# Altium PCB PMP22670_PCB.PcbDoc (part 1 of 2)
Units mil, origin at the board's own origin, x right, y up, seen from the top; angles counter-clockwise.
Board outline 3010.03 x 2810.03 mil, 4 copper layers (Top Layer, GND Layer, Signal Layer, Bottom Layer), stack 61.2 mil thick; 62 components, 17 nets, 102 pads, 238 vias.
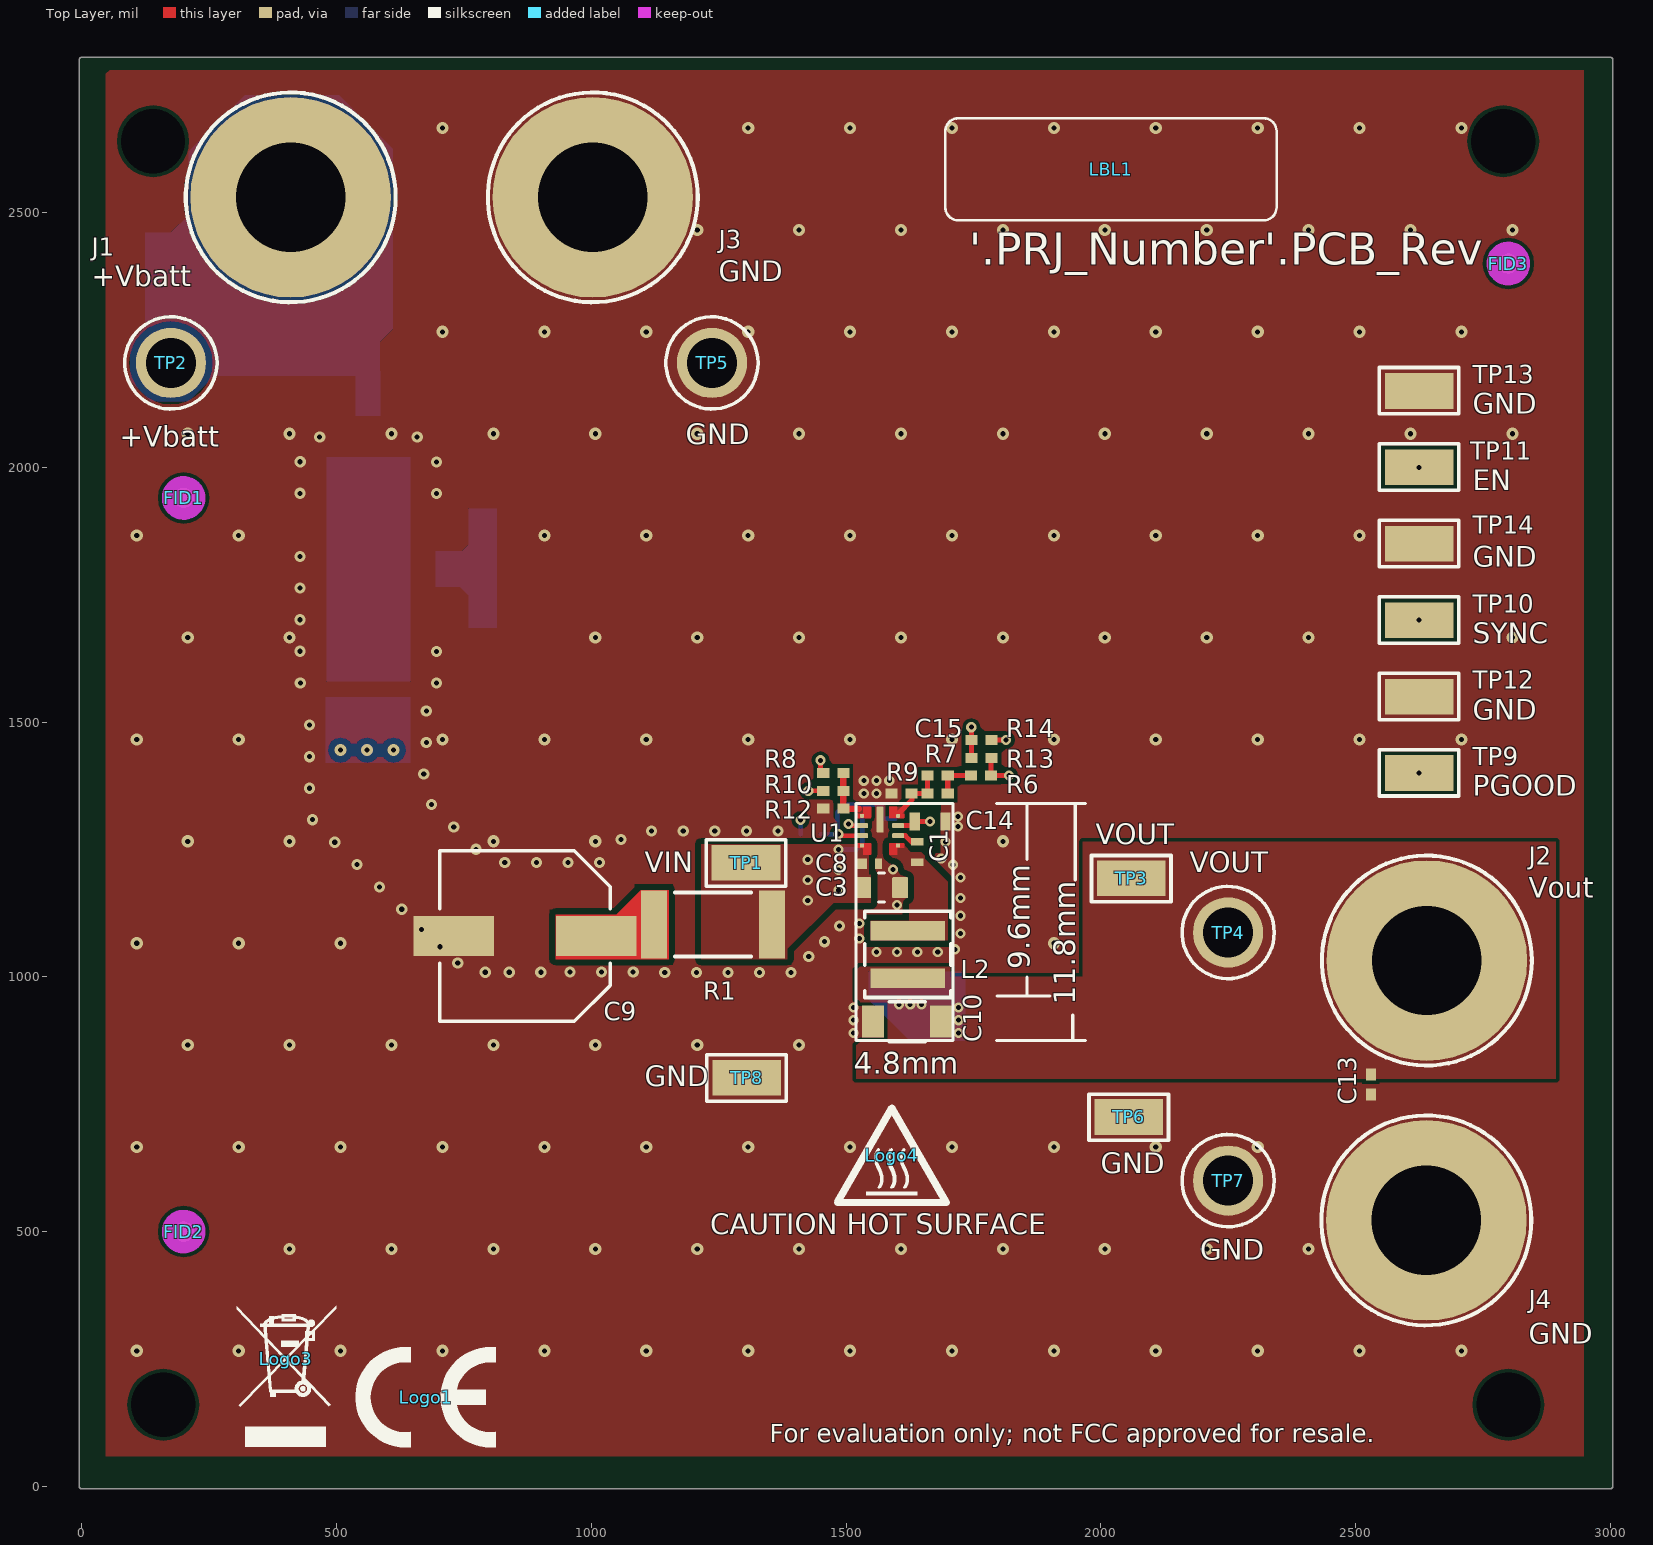
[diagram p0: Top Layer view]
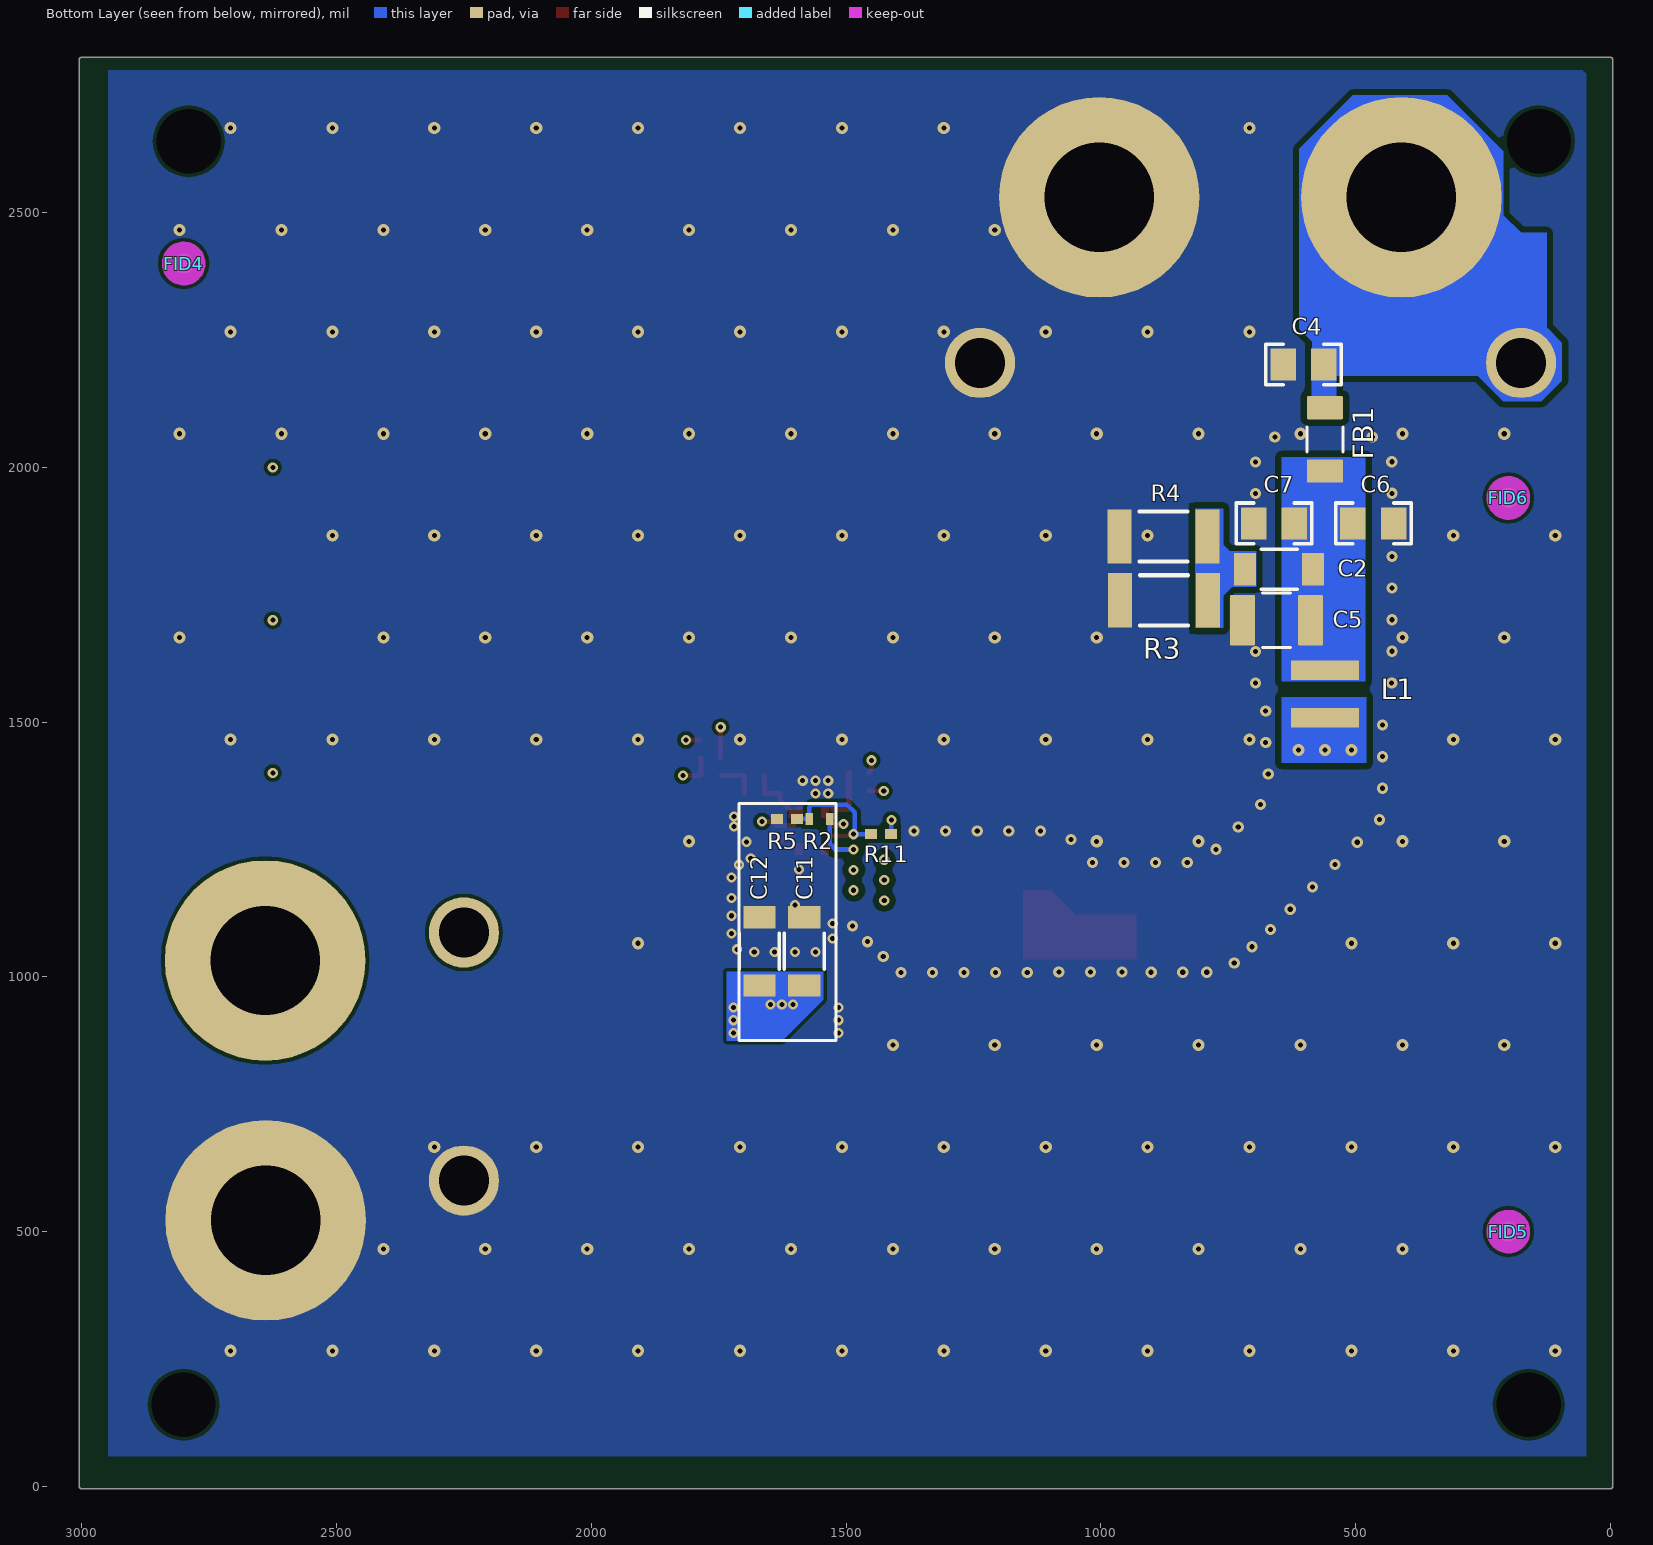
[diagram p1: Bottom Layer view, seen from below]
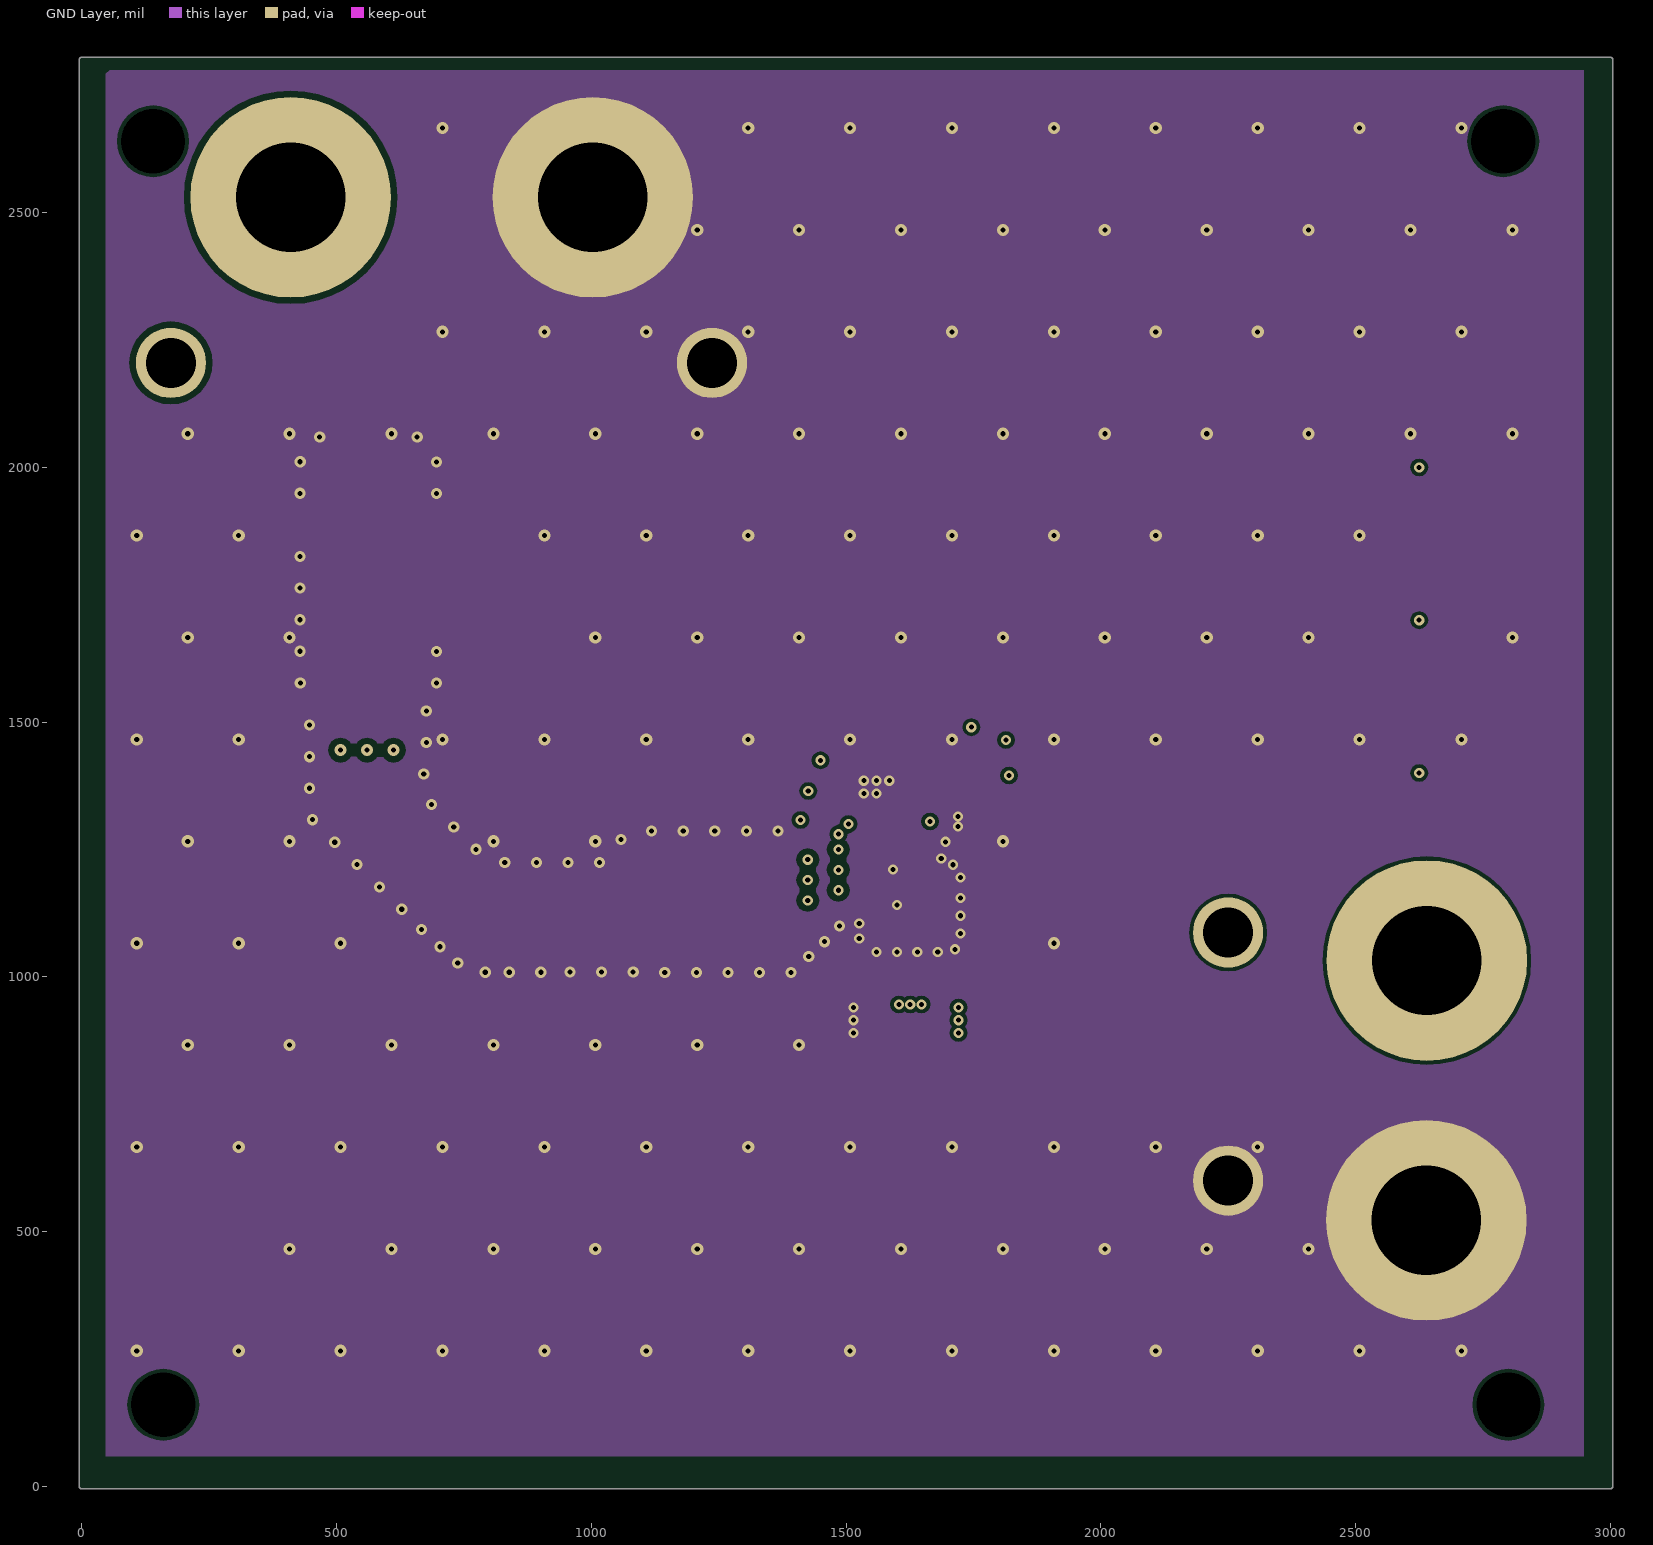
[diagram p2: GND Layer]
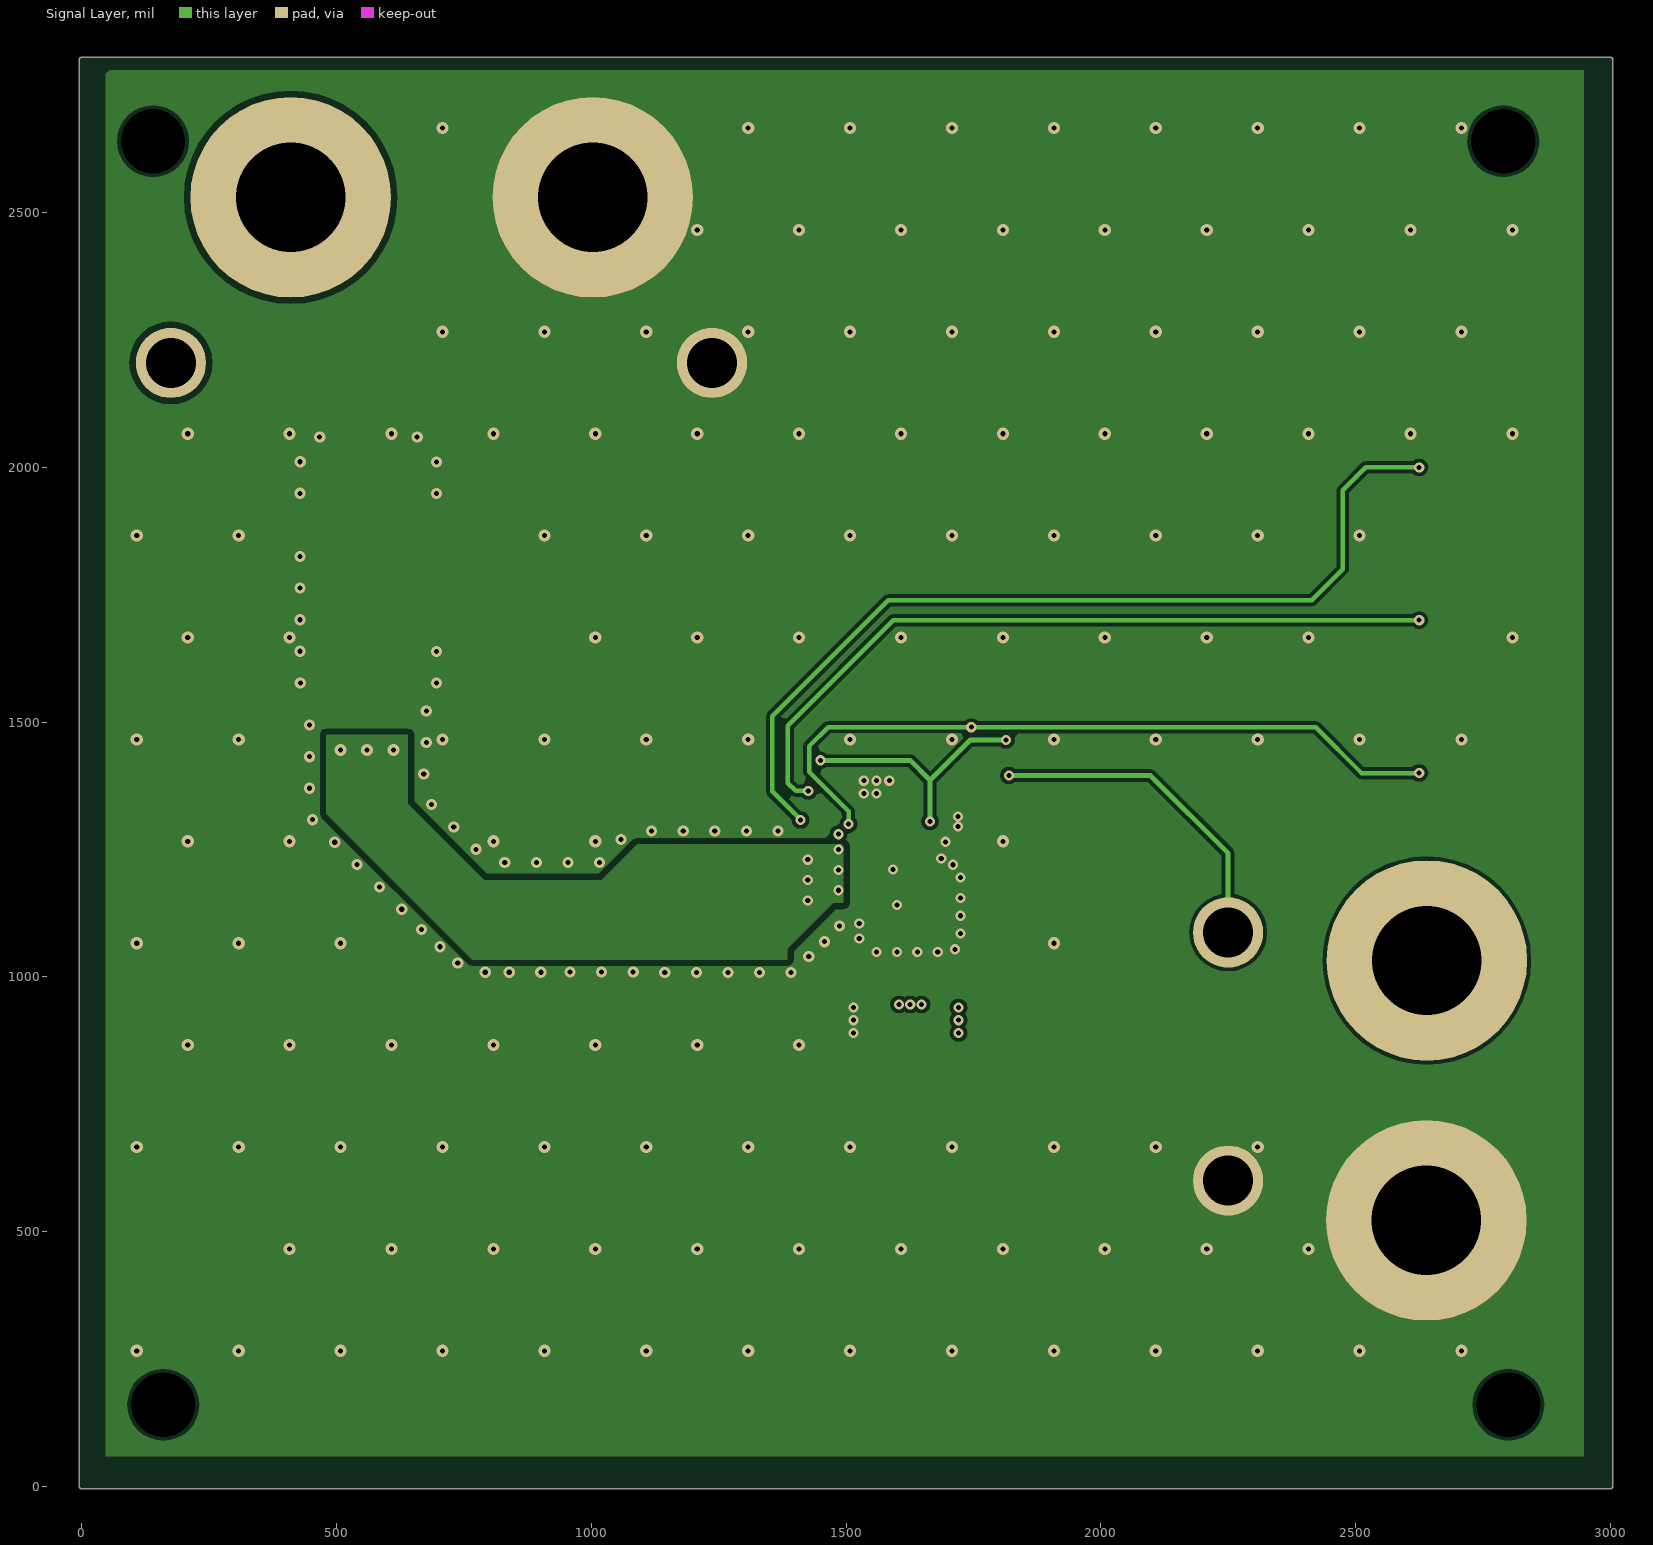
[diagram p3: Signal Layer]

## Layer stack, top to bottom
Top Solder: solder mask 0.4, Solder Resist, Dk 3.5
Top Layer: signal copper 1.4
Dielectric1: core 12.5, FR-4 High Tg, Dk 4.2
GND Layer: signal copper 0.7
Dielectric 2: prepreg 32, FR-4 High Tg, Dk 4.2
Signal Layer: signal copper 0.7
Dielectric 3: core 12.5, FR-4 High Tg, Dk 4.2
Bottom Layer: signal copper 1.4
Bottom Solder: solder mask 0.4, Solder Resist, Dk 3.5

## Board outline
0,-5.02 cw(c0,0) -5.01,0 -5.01,2800 cw(c0,2800) 0,2805.02 2999,2805.02 cw(c2999,2800) 2999.5,2804.99 cw(c3000,2800) 3005.01,2800 3005.01,0 cw(c3000,0) 3000,-5.02

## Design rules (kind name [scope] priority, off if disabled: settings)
AcuteAngle [All] p1: minimum=4.50000000000000E+0001 checktracksonly=FALSE
AssemblyTestPointUsage [All] p1: valid=2
BoardOutlineClearance BoardOutlineClearance_MountingHoles [OnCopper and InComponentClass('Mounting Holes')] p1: gap=40 ignorepadtopadclearanceinfootprint=FALSE
BoardOutlineClearance BoardOutlineClearance_Poly [OnCopper and IsPoly] p2: gap=25 ignorepadtopadclearanceinfootprint=FALSE
BoardOutlineClearance [OnCopper and Not InComponentClass('Logo') and not InComponentClass('FiducialMark') and not InRegion(1000,500,4000,800) and not InPoly] p3: gap=30 ignorepadtopadclearanceinfootprint=FALSE
Clearance Clearance_BottomLayer_Vin [InNamedPolygon('BOTTOM_LAYER_GND') vs (InNet('Vin') OR InNet('VINY') OR InNet('NetC2_2') OR InNet('VINX'))] p1: gap=12 ignorepadtopadclearanceinfootprint=FALSE
Clearance Clearance_SW_1 [InNamedPolygon('TOP_LAYER_SW') vs InNet('GND')] p2: gap=12 ignorepadtopadclearanceinfootprint=FALSE
Clearance Clearance_TopLayer_GND [InNamedPolygon('TOP_LAYER_GND') vs (InNet('Vin') OR InNet('VINX') OR InNet('SW'))] p3: gap=12 ignorepadtopadclearanceinfootprint=FALSE
Clearance Clearance_Midlayer2_GND [InNamedPolygon('SIGNAL_LAYER_GND') vs (InNet('Vin') OR InNet('VINX'))] p4: gap=12 ignorepadtopadclearanceinfootprint=FALSE
Clearance Clearance_Midlayer1_Vin [InNamedPolygon('GND_LAYER_GND') vs (InNet('Vin') OR InNet('VINX'))] p5: gap=12 ignorepadtopadclearanceinfootprint=FALSE
Clearance Clearance_NetC91 [InNamedPolygon('TOP_LAYER_GND') vs InNet('NetC9_1')] p6: gap=12 ignorepadtopadclearanceinfootprint=FALSE
Clearance Clearance_Vin [(InNamedPolygon('Top Layer-Vin')) vs InNet('GND')] p7: gap=12 ignorepadtopadclearanceinfootprint=FALSE
Clearance Clearance_VinPolygon [(InNet('Vin') AND InNamedPolygon('Top Layer-Vin')) vs (InNet('GND') OR InNet('PGOOD'))] p8: gap=12 ignorepadtopadclearanceinfootprint=FALSE
Clearance Clearance_Keepouts [((IsTrack Or IsArc) And Not InPoly) And IsFree and IsKeepOut vs ((IsTrack Or IsArc) And Not InPoly) And IsFree and IsKeepOut] p9: gap=0 ignorepadtopadclearanceinfootprint=FALSE
Clearance Clearance_Poly [InPolygon] p10: gap=7 ignorepadtopadclearanceinfootprint=FALSE
Clearance Clearance_FiducialMark [IsKeepOut and InComponentClass('FiducialMark') vs IsPad and InComponentClass('FiducialMark')] p11: gap=0 ignorepadtopadclearanceinfootprint=FALSE
Clearance [All] p12: gap=7.5 ignorepadtopadclearanceinfootprint=FALSE except(0: Arc-Hole Track-Hole SMDPad-Hole THPad-Hole Via-Hole Fill-Hole Poly-Hole Region-Hole Text-Hole)
ComponentClearance ComponentClearance_MountingHoles_FiducialMarks [InComponentClass('Mounting Holes') vs InComponentClass('FiducialMark')] p1: gap=50 collisioncheckmode=3 verticalgap=10 showdistances=FALSE
ComponentClearance ComponentClearance_Shunt [InComponentClass('Header') vs InComponentClass('Shunt')] p2: gap=0 collisioncheckmode=3 verticalgap=0 showdistances=FALSE
ComponentClearance ComponentClearance_Logo [InComponentClass('Logo')] p3: gap=50 collisioncheckmode=3 verticalgap=10 showdistances=FALSE
ComponentClearance ComponentClearance_ScrewToNut [(HasFootprint('NY PMS 440 0025 PH')) vs (HasFootprint('Keystone_1902C'))] p4: gap=5 collisioncheckmode=3 verticalgap=10 showdistances=FALSE
ComponentClearance ComponentClearance_MountingHoles [InComponentClass('Mounting Holes')] p5: gap=250 collisioncheckmode=3 verticalgap=100000 showdistances=FALSE
ComponentClearance ComponentClearance_SmallPassives [HasFootprint('0201*') or HasFootprint('0402*') or HasFootprint('0508') or HasFootprint('0603*') or HasFootprint('0612') or HasFootprint('0805*') or HasFootprint('0815*') or HasFootprint('0830*') or HasFootprint('1206*') or HasFootprint('1210*') or HasFootprint('1808*') or HasFootprint('1812*') or HasFootprint('1825*') or HasFootprint('2010*') or HasFootprint('2220*') or HasFootprint('2225*') or HasFootprint('2512*') or HasFootprint('2728*') or HasFootprint('3518*') vs HasFootprint('0201*') or HasFootprint('0402*') or HasFootprint('0508') or HasFootprint('0603*') or HasFootprint('0612') or HasFootprint('0805*') or HasFootprint('0815*') or HasFootprint('0830*') or HasFootprint('1206*') or HasFootprint('1210*') or HasFootprint('1808*') or HasFootprint('1812*') or HasFootprint('1825*') or HasFootprint('2010*') or HasFootprint('2220*') or HasFootprint('2225*') or HasFootprint('2512*') or HasFootprint('2728*') or HasFootprint('3518*')] p6: gap=10 collisioncheckmode=3 verticalgap=10 showdistances=FALSE
ComponentClearance ComponentClearance_THtoSMT [IsThruComponent vs IsSMTComponent] p7: gap=40 collisioncheckmode=3 verticalgap=30 showdistances=FALSE
ComponentClearance ComponentClearance_THtoTH [IsThruComponent vs IsThruComponent] p8: gap=30 collisioncheckmode=3 verticalgap=30 showdistances=FALSE
ComponentClearance [All] p9: gap=10 collisioncheckmode=3 verticalgap=10 showdistances=FALSE
DiffPairsRouting [All] p1: maxlimit=100 minlimit=10 mostfreqgap=10 toplayer_minwidth=15 toplayer_maxwidth=15 toplayer_prefwidth=15 midlayer1_minwidth=15 midlayer1_maxwidth=15 midlayer1_prefwidth=15 midlayer2_minwidth=15 midlayer2_maxwidth=15 midlayer2_prefwidth=15 bottomlayer_minwidth=15 bottomlayer_maxwidth=15 bottomlayer_prefwidth=15 maxuncoupledlength=1000
FabricationTestPointUsage TestPointUsage [All] p1: valid=2 allowmultiple=FALSE
FabricationTestpoint Testpoint [All] p1: side=3 testpointundercomponent=TRUE minsize=40 maxsize=100 preferedsize=60 minholesize=0 maxholesize=40 preferedholesize=32 testpointgrid=1 allowsidetop=TRUE allowsidebottom=TRUE usegrid=TRUE gridtolerance=0.01
FanoutControl Fanout_LCC [IsLCC] p1: bgadir=Out bgaviamode=Centered fanoutstyle=Auto fanoutdirection=Alternating viagrid=1 // Fanout_LCC (Default Rule)
FanoutControl Fanout_BGA [IsBGA] p2: bgadir=Out bgaviamode=Centered fanoutstyle=Auto fanoutdirection=Alternating viagrid=1 // Fanout_BGA (Default Rule)
FanoutControl Fanout_Default [All] p4: bgadir=Out bgaviamode=Centered fanoutstyle=Auto fanoutdirection=Alternating viagrid=1 // Fanout_Default (Default Rule)
FanoutControl Fanout_Small [(CompPinCount < 5)] p5: bgadir=Out bgaviamode=Centered fanoutstyle=Auto fanoutdirection=OutThenIn viagrid=1 // Fanout_Small (Default Rule)
HoleSize [All] p1: absolutevalues=TRUE maxlimit=251 minlimit=7.87 maxpercent=80.000 minpercent=20.000
MinimumAnnularRing MinimumAnnularRing_ThermalPadVias [IsVia and InAnyComponent] p1: minimumring=5
MinimumAnnularRing [All] p2: minimumring=5
MinimumSolderMaskSliver MinimumSolderMaskSliver_Logo [InComponentClass('Logo') vs InComponentClass('Logo')] p1: minsoldermaskwidth=0.7
MinimumSolderMaskSliver [All] p2: minsoldermaskwidth=3.94
PlaneClearance [All] p1: clearance=8
PlaneConnect [All] p1: planeconnectstyle=Direct reliefexpansion=10 reliefentries=4 reliefconductorwidth=10 reliefairgap=10
PolygonConnect [All] p1: connectstyle=Direct reliefconductorwidth=10 reliefentries=4 polygonreliefangle="90 Angle" airgapwidth=10
RoutingVias ThermalPadVias [IsVia and InAnyComponent] p1: holewidth=8 width=16 viastyle="Through Hole" minholewidth=7.87 minwidth=10 maxholewidth=12.99 maxwidth=30
RoutingVias [All] p2: holewidth=8 width=16 viastyle="Through Hole" minholewidth=7.87 minwidth=15 maxholewidth=40 maxwidth=65
SilkToBoardRegionClearance [Not ((IsComment or IsDesignator) And (Hide <> 'False')) and not InRegion(1000,500,4000,800)] p1:
SilkToSilkClearance SilkToSilkClearance_Pb-FreeLogo [(HasFootprint('Pb-Free_Overlay_Medium') OR HasFootprint('Pb-Free_Overlay_Small')) vs (HasFootprint('Pb-Free_Overlay_Medium') OR HasFootprint('Pb-Free_Overlay_Small'))] p1: silktosilkclearance=0
SilkToSilkClearance [All] p2: silktosilkclearance=0
SilkToSolderMaskClearance SilkToComponentPadClearance [(IsPad or IsFill or IsRegion) and InAnycomponent] p1: minsilkscreentomaskgap=0 clearancetoexposedcopper=TRUE
SilkToSolderMaskClearance "Silk to Solder Mask Opening" [All] p2: minsilkscreentomaskgap=0 clearancetoexposedcopper=FALSE
SolderMaskExpansion [All] p1: expansion=1.97
Width [All] p1: maxlimit=100 minlimit=6 preferedwidth=10
14 further rules are at their usual default settings.

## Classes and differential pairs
component class FiducialMark: FID1 FID2 FID3 FID4 FID5 FID6
component class PMP22670_Schematic: C1 C2 C3 C4 C5 C6 C7 C8 C9 C10 C11 C12 C13 C14 C15 CVCC FB1 J1 J2 J3 J4 L L1 L2 R1 R2 R3 R4 R5 R6 R7 R8 R9 R10 R11 R12 R13 R14 R? TP1 TP2 TP3 TP4 TP5 TP6 TP7 TP8 TP9 TP10 TP11 TP12 TP13 TP14 U1
component class Label: LBL1
component class PMP22670_Hardware: FID1 FID2 FID3 FID4 FID5 FID6 LBL1 Logo1 Logo2 Logo3 Logo4

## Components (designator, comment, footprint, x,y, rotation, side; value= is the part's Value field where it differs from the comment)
C1 "CGA2B3X7R1E104K050BB" 0402S 1640,1245 r270 top value=0.1uF
C2 "CGA5L2X7R2A105K160AA" 1206_180 650,1800 r0 bottom value=1uF
C3 "CGA4J1X7R1H475K125AC" FP-CGA4J1X7R1H475K125AC_0805-MFG 1570,1175 r180 top value=4.7µF
C4 "DNP" 0805_HV 602,2202 r0 bottom value=0.1uF
C5 "HMF325B7225KMHP" FP-HMF325B7225KMHP_1210-MFG 655,1700 r180 bottom
C6 "" 0805_HV 465,1890 r180 bottom value=0.1uF
C7 "" 0805_HV 660,1890 r0 bottom value=0.1uF
C8 "CGA2B3X7R1H104K050BB" 0402L#1 1549,1222 r0 top value=0.1uF
C9 "" SM_RADIAL_F 870,1080 r180 top value=22uF
C10 "" 1206_180 1620,912 r0 top value=22uF
C11 "" 1206_180 1582,1050 r270 bottom value=22uF
C12 "" 1206_180 1670,1050 r270 bottom value=22uF
C13 "GCM155R71H102KA37D" 0402L#2 2530,789 r90 top value=1000pF
C14 "CGA3E1X7R1C105K080AC" 0603S 1665,1305 r0 top value=1uF
C15 "DNP" 0402L#2 1680,1395 r180 top value=10pF
FB1 "BLM31KN471SH1L" FP-BLM31KN471SH1L_1206-MFG 560,2055 r270 bottom
FID1 "Fiducial" Fiducial10-20 200,1940 r0 top
FID2 "Fiducial" Fiducial10-20 200,500 r0 top
FID3 "Fiducial" Fiducial10-20 2800,2400 r0 top
FID4 "Fiducial" Fiducial10-20 2800,2400 r180 bottom
FID5 "Fiducial" Fiducial10-20 200,500 r180 bottom
FID6 "Fiducial" Fiducial10-20 200,1940 r180 bottom
J1 "+Vbatt" Keystone575-8 410,2530 r90 top
J2 "Vout" Keystone575-8 2640,1032 r90 top
J3 "GND" Keystone575-8 1003,2530 r90 top
J4 "GND" Keystone575-8 2639,522 r90 top
L1 "XAL4020-601MEB" XAL4020 560,1555 r90 bottom value=600nH
L2 "XAL4030-332MEB" XAL4030 1621,1044 r90 top value=3.3uH
LBL1 "THT-14-423-10" Label_650x200 2020,2585 r180 top
Logo1 "CE Mark" CE_Mark_5mm 675,175 r0 top
Logo2 "FCC disclaimer" FCC_disclaimer 3330,495 r180 top
Logo3 "WEEE logo" WEEE_Minimum 400,250 r0 top
Logo4 "CAUTION HOT SURFACE" IEC_HotSurface_Small 1590,650 r0 top
R1 "CRCW25120000Z0EG" 2512 1239,1103 r0 top value=0
R2 "CRCW04021M65FKED" 0402S 1552,1310 r180 bottom value=1.65Meg
R3 "CRCW201010R0FKEF" 2010L 876,1739 r180 bottom value=10.0
R4 "CRCW201010R0FKEF" 2010L 877,1864 r180 bottom value=10.0
R5 "CRCW0402100KFKED" 0402L#2 1616,1310 r180 bottom value=100k
R6 "" 0402L#2 1765,1395 r0 top value=0
R7 "CRCW04020000Z0ED" 0402L#2 1680,1360 r0 top value=0
R8 "DNP" 0402L#2 1475,1400 r0 top value=0
R9 "DNP" 0402L#2 1609,1360 r180 top value=24.9k
R10 "DNP" 0402L#2 1475,1365 r0 top value=0
R11 "" 0402L#2 1431,1280 r0 bottom value=0
R12 "" 0402L#2 1475,1330 r180 top value=0
R13 "DNP" 0402L#2 1766,1430 r0 top value=100k
R14 "CRCW0402100KJNED" 0402L#2 1766,1465 r180 top value=100k
TP1 "VIN" Testpoint_Keystone_Miniature 1304,1224 r0 top
TP2 "+Vbatt" Keystone1502-2 175,2205 r90 top
TP3 "VOUT" Testpoint_Keystone_Miniature 2059.87,1193.22 r0 top
TP4 "VOUT" Keystone1502-2 2250,1087 r270 top
TP5 "GND" Keystone1502-2 1237,2205 r90 top
TP6 "GND" Testpoint_Keystone_Miniature 2055,725 r0 top
TP7 "GND" Keystone1502-2 2250,600 r90 top
TP8 "GND" Testpoint_Keystone_Miniature 1305,802 r0 top
TP9 "PGOOD" Testpoint_Keystone_Miniature 2625,1400 r180 top
TP10 "SYNC" Testpoint_Keystone_Miniature 2625,1700 r180 top
TP11 "EN" Testpoint_Keystone_Miniature 2625,2000 r180 top
TP12 "GND" Testpoint_Keystone_Miniature 2625,1550 r180 top
TP13 "GND" Testpoint_Keystone_Miniature 2625,2150 r180 top
TP14 "GND" Testpoint_Keystone_Miniature 2625,1850 r180 top
U1 "LMR43620MSC3RPERQ1" RPE0009A 1566.96,1286.89 r0 top

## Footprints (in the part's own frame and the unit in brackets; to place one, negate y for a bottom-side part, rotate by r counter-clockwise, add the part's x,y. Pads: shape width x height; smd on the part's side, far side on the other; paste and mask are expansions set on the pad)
0402L#1 [mm] "0402 from SM-752 data"
  rect 0.6x0.5 smd: 1(-0.5,0)
  rect 0.346x0.5 smd: 2(0.373,0)
  body extent -0.55,-0.3 0.55,0.3, height 0.6
0402L#2 [mm] "0402 from SM-752 data"
  rect 0.6x0.5 smd: 1(-0.5,0) 2(0.5,0)
  body extent -0.55,-0.3 0.55,0.3, height 0.6
0402S [mil] "Based on C0402S footprint from PADS legacy"
  rect 15x24 smd: 1(-20,0) 2(20,0)
  body extent -22,-12 22,12, height 24
0603S [mil]
  rect 20x35 smd: 1(-30,0) 2(30,0)
  body extent -34,-19 34,19, height 39
0805_HV [mil] "0805 with 30mil clearance between pads"
  rect 50x63 smd: 1(-40,0) 2(40,0)
  silkscreen extent -74,-40 74,40, body extent -43,-29 43,29, height 57
1206_180 [mm] "1206_180"
  rect 1.1x1.6 smd: 1(-1.7,0) 2(1.7,0)
  silkscreen extent -0.9,-1 0.9,1, body extent -1.75,-0.95 1.75,0.95, height 1.8
2010L [mm]
  rect 1.2x2.7 smd: 1(-2.2,0) 2(2.2,0)
  silkscreen extent -1.2,-1.25 1.2,1.25, body extent -2.73,-1.45 2.73,1.45, height 1.66
2512 [mm] "Chip Resistor, Body 6.3x3.2mm, IPC Medium Density"
  rect 1.3x3.4 smd: 1(-2.95,0) 2(2.95,0)
  silkscreen extent -1.9,-1.6 1.9,1.6, body extent -3.22,-1.67 3.22,1.67, height 0.71
CE_Mark_5mm [mil] "Minimum text height for CE Mark"
  silkscreen extent -138,-98 138,98
FCC_disclaimer [mil]
Fiducial10-20 [mm]
  round 1 smd mask+0.5: 1(0,0)
  Top Layer keep-out circle w1.178: c0,0 r0.5
FP-BLM31KN471SH1L_1206-MFG [mm]
  rrect9% 1.15x1.8 smd paste+0 mask+0: 1(-1.575,0) 2(1.575,0)
  silkscreen extent -0.63,-0.9 0.63,0.9, body extent -1.6,-0.8 1.6,0.8, height 1.8
FP-CGA4J1X7R1H475K125AC_0805-MFG [mm]
  rrect13% 0.8x1.05 smd paste+0 mask+0: 1(-0.925,0) 2(0.925,0)
  silkscreen extent -0.15,-0.72 0.15,0.72, body extent -1.43,-0.82 1.43,0.82, height 0.25
FP-HMF325B7225KMHP_1210-MFG [mm]
  rrect8% 1.25x2.5 smd paste+0 mask+0: 1(-1.7,0) 2(1.7,0)
  silkscreen extent -0.7,-1.35 0.7,1.35, body extent -1.6,-1.25 1.6,1.25, height 2.7
IEC_HotSurface_Small [mil]
  silkscreen extent -107,-93 107,92
Keystone575-8 [mm] "Banana Jack"
  round 10 hole 5.45: 1(0,0)
  silkscreen extent -5.23,-5.23 5.23,5.23, body extent -3.92,-3.94 3.95,3.94, height 2.36
Keystone1502-2 [mm] "Double Turret"
  round 3.5 hole 2.5: 1(0,0)
  silkscreen extent -2.3,-2.3 2.3,2.3, body extent -1.6,-1.6 1.59,1.6, height 5.62
Label_650x200 [mil] "Thermal Transfer Label"
  round 1 on Mech13: 0(0,0)
  silkscreen extent -325,-100 325,100, body extent -325,-100 325,100, height 1
RPE0009A [mm] "VQFN, 9-Leads, Body 2x2.mm"
  rrect50% 0.2x0.2 smd paste+0: 1(-0.9,0.738) 4(-0.9,-0.738) 5(0.9,-0.738) 8(0.9,0.738)
  rrect40% 0.6x0.25 smd: 2(-0.9,0.25) 3(-0.9,-0.25) 6(0.9,-0.25) 7(0.9,0.25)
  rrect29% 0.35x1.3 smd paste-0.35: 9(0,0.55)
  Top Layer region: 1.2,-0.676 1.2,-0.801 1.196,-0.82 1.185,-0.836 1.169,-0.847 1.15,-0.851 1.15,-0.851 0.9,-0.851 0.881,-0.854 0.865,-0.865 0.854,-0.881 0.85,-0.901 0.85,-0.901 0.85,-1.151 0.846,-1.17 0.835,-1.186 0.819,-1.197 0.8,-1.201 0.8,-1.201 0.5,-1.201 0.481,-1.197 0.465,-1.186 0.454,-1.17 0.45,-1.151 0.45,-1.151 0.45,-0.676 0.454,-0.656 0.465,-0.64 0.481,-0.629 0.5,-0.626 0.5,-0.626 1.15,-0.626 1.169,-0.629 1.185,-0.64 1.196,-0.656 1.2,-0.676
  Top Layer region: -1.2,-0.676 -1.2,-0.801 -1.196,-0.82 -1.185,-0.836 -1.169,-0.847 -1.15,-0.851 -1.15,-0.851 -0.9,-0.851 -0.881,-0.854 -0.865,-0.865 -0.854,-0.881 -0.85,-0.901 -0.85,-0.901 -0.85,-1.151 -0.846,-1.17 -0.835,-1.186 -0.819,-1.197 -0.8,-1.201 -0.8,-1.201 -0.5,-1.201 -0.481,-1.197 -0.465,-1.186 -0.454,-1.17 -0.45,-1.151 -0.45,-1.151 -0.45,-0.676 -0.454,-0.656 -0.465,-0.64 -0.481,-0.629 -0.5,-0.626 -0.5,-0.626 -1.15,-0.626 -1.169,-0.629 -1.185,-0.64 -1.196,-0.656 -1.2,-0.676
  Top Layer region: 1.2,0.676 1.2,0.801 1.196,0.82 1.185,0.836 1.169,0.847 1.15,0.851 1.15,0.851 0.9,0.851 0.881,0.854 0.865,0.865 0.854,0.881 0.85,0.901 0.85,0.901 0.85,1.151 0.846,1.17 0.835,1.186 0.819,1.197 0.8,1.201 0.8,1.201 0.5,1.201 0.481,1.197 0.465,1.186 0.454,1.17 0.45,1.151 0.45,1.151 0.45,0.676 0.454,0.656 0.465,0.64 0.481,0.629 0.5,0.626 0.5,0.626 1.15,0.626 1.169,0.629 1.185,0.64 1.196,0.656 1.2,0.676
  Top Layer region: -1.2,0.676 -1.2,0.801 -1.196,0.82 -1.185,0.836 -1.169,0.847 -1.15,0.851 -1.15,0.851 -0.9,0.851 -0.881,0.854 -0.865,0.865 -0.854,0.881 -0.85,0.901 -0.85,0.901 -0.85,1.151 -0.846,1.17 -0.835,1.186 -0.819,1.197 -0.8,1.201 -0.8,1.201 -0.5,1.201 -0.481,1.197 -0.465,1.186 -0.454,1.17 -0.45,1.151 -0.45,1.151 -0.45,0.676 -0.454,0.656 -0.465,0.64 -0.481,0.629 -0.5,0.626 -0.5,0.626 -1.15,0.626 -1.169,0.629 -1.185,0.64 -1.196,0.656 -1.2,0.676
  body extent -1,-1 1,1, height 1
SM_RADIAL_F [mm] "8 x 10.2mm:  Panasonic F"
  rect 4x2 smd: 1(-3.55,0) 2(3.55,0)
  silkscreen extent -4.25,-4.25 4.25,4.25, body extent -4.25,-4.25 4.25,4.25, height 10.5
Testpoint_Keystone_Miniature [mil] "Miniature SMT test point"
  rect 135x70 smd: 1(0,0)
  silkscreen extent -78,-46 78,45, body extent -52,-20 52,20, height 61
WEEE_Minimum [mil] "WEEElie bin"
  silkscreen extent -95,-172 99,104
XAL4020 [mm] "Coilcraft XAL4020 01/14/18"
  rrect10% 0.98x3.4 smd: 1(-1.185,0) 2(1.185,0)
  body extent -2.15,-2.15 2.15,2.15, height 2.11
XAL4030 [mil] "Coilcraft XAL4030 7/18/12"
  rect 38x146 smd: 1(-46.5,0) 2(46.5,0)
  silkscreen extent -84,-84 84,84, body extent -84,-84 84,84, height 122

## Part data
C1: library part CMP-0080610-1, "CAP, CERM, 0.1 µF, 25 V,+/- 10%, X7R, AEC-Q200 Grade 1, 0402", Cap_Case=0402, Manufacturer=TDK, Supplier Part Number 1=445-6902-1-ND, TempCo=X7R, Tolerance_%=10%, Value2=25V, ValueDisplayed=0.1µF
C2: library part CMP-0008779-2, "CAP, CERM, 1 uF, 100 V, +/- 10%, X7R, AEC-Q200 Grade 1, 1206", Cap_Case=1206_180, Manufacturer=TDK, Supplier Part Number 1=445-5845-1-ND, TempCo=X7R, Tolerance_%=10%, Value1="0.004575 ohm", Value2=100V, ValueDisplayed=1uF
C3: library part CMP-0090082-1, "Cap Ceramic 4.7uF 50V X7R 10% Pad SMD 0805 +125°C Automotive T/R", Manufacturer="TDK Corporation", Operating Temperature Range="-55°C to +125°C", TempCo=15%, Temperature Characteristic=X7R, Tolerance_%=0.1%, ValueDisplayed=4.7uF
C4 C6 C7: library part CMP-0007969-2, "CAP, CERM, 0.1 uF, 100 V, +/- 10%, X7R, AEC-Q200 Grade 1, 0805", Cap_Case=0805, Manufacturer=TDK, PartNumber=CGA4J2X7R2A104K125AA, Supplier Part Number 1=445-5827-1-ND, TempCo=X7R, Tolerance_%=10%, Value1="0.020726 ohm", Value2=100V, ValueDisplayed=0.1uF
C5: library part CMP-0089259-1, "2.2µF ±10% 100V Ceramic Capacitor X7R 1210 (3225 Metric)", Digikey Part Number=587-6465-1-ND, Manufacturer="Taiyo Yuden", Mouser Part Number=963-HMF325B7225KMHP, Operating Temperature Range="-55°C to +125°C", TempCo=15%, Temperature Characteristic=X7R, Tolerance_%=10%, ValueDisplayed=2.2uF
C8: library part CMP-0006325-2, "CAP, CERM, 0.1 uF, 50 V, +/- 10%, X7R, AEC-Q200 Grade 1, 0402", Cap_Case=0402, Manufacturer=TDK, Supplier Part Number 1=445-6899-1-ND, TempCo=X7R, Tolerance_%=10%, Value1="0.039064 ohm", Value2=50V, ValueDisplayed=0.1uF
C9: library part CMP-0011202-2, "CAP, AL, 22 uF, 100 V, +/- 20%, 1.3 ohm, AEC-Q200 Grade 2, SMD", Cap_Case=F, Manufacturer=Panasonic, PartNumber=EEE-FK2A220P, Supplier Part Number 1=PCE3845CT-ND, Tolerance_%=20%, Value1="1.3 ohm", Value2=100V, ValueDisplayed=22uF
C10 C11 C12: library part CMP-0008811-2, "CAP, CERM, 22 uF, 10 V, +/- 10%, X7R, AEC-Q200 Grade 1, 1206", Cap_Case=1206, Manufacturer=MuRata, PartNumber=GCM31CR71A226KE02, TempCo=X7R, Tolerance_%=10%, Value1=Unknown, Value2=10V, ValueDisplayed=22uF
C13: library part CMP-0006354-2, "CAP, CERM, 1000 pF, 50 V, +/- 10%, X7R, AEC-Q200 Grade 1, 0402", Cap_Case=0402, Manufacturer=MuRata, Supplier Part Number 1=490-4761-1-ND, TempCo=X7R, Tolerance_%=10%, Value1=Unknown, Value2=50V, ValueDisplayed=1000pF
C14: library part CMP-0079607-1, "CAP, CERM, 1 µF, 16 V,+/- 10%, X7R, AEC-Q200 Grade 1, 0603", Cap_Case=0603, Manufacturer=TDK, Supplier Part Number 1=445-12539-1-ND, TempCo=X7R, Tolerance_%=10%, Value2=16V, ValueDisplayed=1µF
C15: library part CMP-0860290-1, "CAP, CERM, 10 pF, 50 V,+/- 5%, C0G/NP0, AEC-Q200 Grade 1, 0402", Cap_Case=0402, Manufacturer=MuRata, PartNumber=GCM1555C1H100JA16D, TempCo=C0G/NP0, Tolerance_%=5%, Value2=50V, ValueDisplayed=10pF
FB1: library part CMP-0090407-1, "470 Ohms @ 100MHz 1 Power Line Ferrite Bead 1206 (3216 Metric) 4A 20mOhm", Digikey Part Number=490-16529-1-ND, Impedance At Frequency="470O @ 100MHz", Manufacturer=Murata, Mouser Part Number=81-BLM31KN471SH1L, Operating Temperature Range="-55°C to +125°C", Tolerance_%=25%
FID1 FID2 FID3 FID4 FID5 FID6: library part CMP-0077181-1, "Fiducial mark.  There is nothing to buy or mount.", Manufacturer=N/A
J1 J2 J3 J4: library part CMP-0055166-2, "Standard Banana Jack, Uninsulated, 8.9mm", Manufacturer=Keystone, PartNumber=575-8, Supplier Part Number 1=36-575-8-ND
L1: library part CMP-0060988-2, "Inductor, Shielded, Composite, 600 nH, 10.38 A, 0.01 ohm, AEC-Q200 Grade 1, SMD", Manufacturer=Coilcraft, Value1="0.01 ohm", Value2=10.38A, ValueDisplayed=600nH
L2: library part CMP-0060989-1, "Inductor, Shielded, Composite, 3.3 uH, 5.5 A, 0.026 ohm, SMD", Manufacturer=Coilcraft, Supplier Part Number 1=994-XAL4030-332MEB, Value1="0.026 ohm", Value2=5.5A, ValueDisplayed=3.3uH
LBL1: library part CMP-0003625-1, "Thermal Transfer Printable Labels, 0.650\" W x 0.200\" H - 10,000 per roll", Manufacturer=Brady, Supplier Part Number 1=97C5133
Logo1: library part CMP-0074844-1
Logo2: library part CMP-0074847-1, "FCC_disclaimer"
Logo3: library part CMP-0074769-1
Logo4: library part CMP-0074837-1, "IEC 61010-1 Hot Surface Warning"
R1: library part CMP-0015864-3, "RES, 0, 5%, 1 W, AEC-Q200 Grade 0, 2512", Manufacturer=Vishay-Dale, Power_W=1W, Supplier Part Number 1=541-0.0XCT-ND, TempCo=ppm/C, Tolerance_%=5%, Value_Code=0000, ValueDisplayed=0
R2: library part CMP-0026121-2, "RES, 1.65 M, 1%, 0.063 W, AEC-Q200 Grade 0, 0402", Manufacturer=Vishay-Dale, Power_W=63mW, Supplier Part Number 1=541-1.65MLCT-ND, TempCo="100 ppm/C", Tolerance_%=1%, Value2=0.063W, Value_Code=1M65, ValueDisplayed=1.65M
R3 R4: library part CMP-0016215-3, "RES, 10.0, 1%, 0.75 W, AEC-Q200 Grade 0, 2010", Manufacturer=Vishay-Dale, Power_W=750mW, Supplier Part Number 1=541-10.0ACCT-ND, TempCo="100 ppm/C", Tolerance_%=1%, Value2=0.75W, Value_Code=10R0, ValueDisplayed=10.0
R5: library part CMP-0025950-3, "RES, 100 k, 1%, 0.063 W, AEC-Q200 Grade 0, 0402", Manufacturer=Vishay-Dale, Power_W=63mW, Supplier Part Number 1=541-100KLCT-ND, TempCo="100 ppm/C", Tolerance_%=1%, Value2=0.063W, Value_Code=100k
R6 R8 R10 R11 R12: library part CMP-0026822-3, "RES, 0, 5%, 0.063 W, AEC-Q200 Grade 0, 0402", Manufacturer=Vishay-Dale, PartNumber=CRCW04020000Z0ED, Power_W=63mW, Supplier Part Number 1=541-0.0JCT-ND, TempCo="200 ppm/C", Tolerance_%=5%, Value2=0.063W, Value_Code=0000, ValueDisplayed=0
R7: library part CMP-0026822-3, "RES, 0, 5%, 0.063 W, AEC-Q200 Grade 0, 0402", Manufacturer=Vishay-Dale, Power_W=63mW, Supplier Part Number 1=541-0.0JCT-ND, TempCo="200 ppm/C", Tolerance_%=5%, Value2=0.063W, Value_Code=0000, ValueDisplayed=0
R9: library part CMP-0026196-2, "RES, 24.9 k, 1%, 0.063 W, AEC-Q200 Grade 0, 0402", Manufacturer=Vishay-Dale, PartNumber=CRCW040224K9FKED, Power_W=63mW, Supplier Part Number 1=541-24.9KLCT-ND, TempCo="100 ppm/C", Tolerance_%=1%, Value2=0.063W, Value_Code=24k9, ValueDisplayed=24.9k
R13: library part CMP-0026823-3, "RES, 100 k, 5%, 0.063 W, AEC-Q200 Grade 0, 0402", Manufacturer=Vishay-Dale, PartNumber=CRCW0402100KJNED, Power_W=63mW, Supplier Part Number 1=541-100KJCT-ND, TempCo="200 ppm/C", Tolerance_%=5%, Value2=0.063W, Value_Code=100k
R14: library part CMP-0026823-3, "RES, 100 k, 5%, 0.063 W, AEC-Q200 Grade 0, 0402", Manufacturer=Vishay-Dale, Power_W=63mW, Supplier Part Number 1=541-100KJCT-ND, TempCo="200 ppm/C", Tolerance_%=5%, Value2=0.063W, Value_Code=100k
TP1 TP3 TP6 TP8 TP9 TP10 TP11 TP12 TP13 TP14: library part CMP-0055152-1, "Test Point, Miniature, SMT", Manufacturer=Keystone, PartNumber=5015, Supplier Part Number 1=36-5015TR-ND
TP2 TP4 TP5 TP7: library part CMP-0055113-1, "Terminal, Turret, TH, Double", Manufacturer=Keystone, PartNumber=1502-2, Supplier Part Number 1=36-1502-2-ND
U1: library part CMP-0860883-2, "Industry's lowest Iq 36V 2.0A/1.0A –DC Synchronous Buck Regulator, RPE0009A (VQFN-9)", Alternate Manufacturer="Texas Instruments"

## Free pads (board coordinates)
  round 60 hole 126: 1(140,2640) 1(160,160) 1(2790,2640) 1(2800,160)

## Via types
v1: diameter 24, hole 10, Top Layer to Bottom Layer, tented both sides, 134 vias
v2: diameter 22, hole 10, Top Layer to Bottom Layer, tented both sides, 54 vias
v3: diameter 20, hole 10, Top Layer to Bottom Layer, tented both sides, 47 vias
v4: diameter 20, hole 10, Top Layer to Bottom Layer, tented bottom, 3 vias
